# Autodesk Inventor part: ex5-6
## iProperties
Author: Administrator
Created: 2001-09
Part Number: ex5-6
Document SubType Name: Modeling
Designer: Administrator
Control State: 0
Master: False
Checked Out: False
PropertySet Name: Design Tracking Control
Length Units: 11272
Angle Units: 11279
Time Units: 11290
Mass Units: 11286
Shininess: 3
Angle Display Precision: 2
Document Length Units: 11272
Document Angle Units: 11286
Document Time Units: 11279
Document Mass Units: 11290
Document Length Units Precision: 3
Document Angle Units Precision: 2
Compacted: False
PropertySet Name: _Private Model Information
Density: 0.0
Volumn: 0.0
Area: 0.0
PropertySet Name: Model Information
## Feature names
1. Revolution1
2. Hole1
3. Shell1
4. Loft1
5. Sweep1
